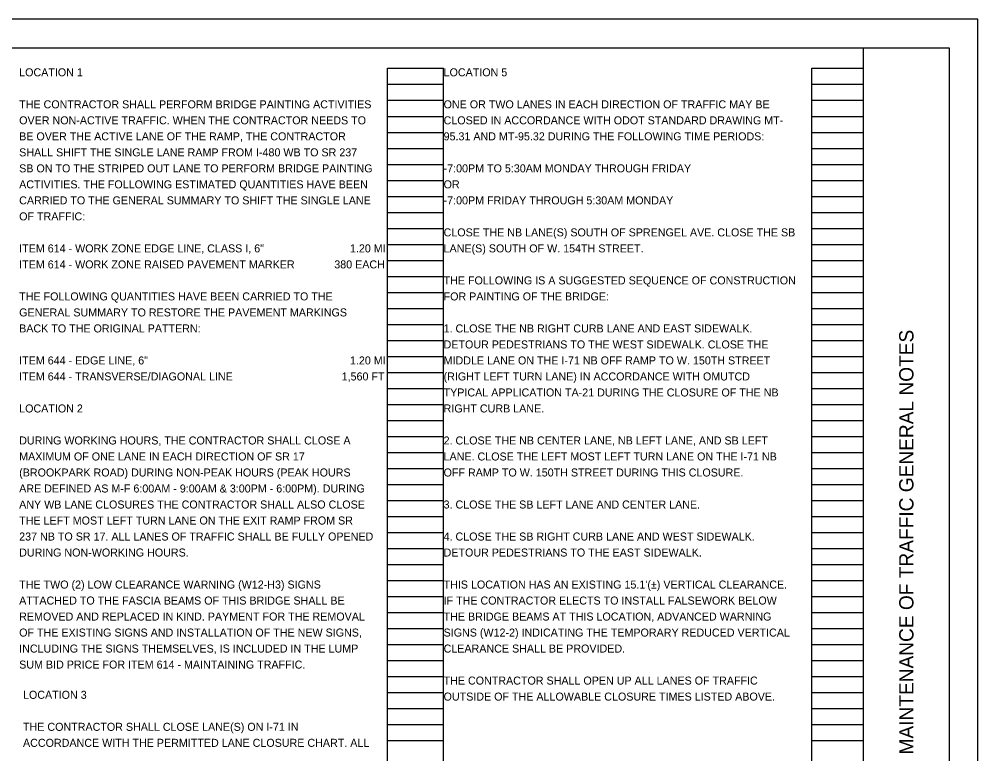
# Model space of a CAD drawing. Extents: x -0.2 to 33.8, y 0.1 to 22.1.
# Drawn here: x 17.04 to 33.8, y 9.27 to 22.12 of the extents above; entities that cross this region are included whole.
import ezdxf

# ---------------------------------------------------------------- set-up
doc = ezdxf.new("R2010")
doc.units = 0
for name, color, linetype in [('SH_Border', 7, 'Continuous'), ('SH_Cut_Line', 7, 'Continuous'), ('SH_Data', 7, 'Continuous'), ('SH_Text', 7, 'Continuous')]:
    doc.layers.add(name, color=color, linetype=linetype)

msp = doc.modelspace()

# ---------------------------------------------------------------- linework, layer by layer
at = {"layer": 'SH_Border'}
msp.add_line((31.798, 0.621), (31.798, 21.621), dxfattribs=at)
msp.add_lwpolyline([(1.298, 21.621), (33.298, 21.621), (33.298, 0.621), (1.298, 0.621)], close=True, dxfattribs=at)
at = {"layer": 'SH_Cut_Line'}
msp.add_lwpolyline([(-0.202, 0.121), (33.798, 0.121), (33.798, 22.121), (-0.202, 22.121)], close=True, dxfattribs=at)
at = {"layer": 'SH_Data'}
for p, q in [((23.478, 1.101), (23.478, 21.261)), ((23.478, 21.261), (24.458, 21.261)), ((24.458, 1.101), (24.458, 21.261)), ((30.898, 1.101), (30.898, 21.261)), ((30.898, 21.261), (31.798, 21.261)), ((31.798, 1.101), (31.798, 21.261)), ((23.478, 20.981), (24.458, 20.981)), ((30.898, 20.981), (31.798, 20.981)), ((23.478, 20.701), (24.458, 20.701)), ((30.898, 20.701), (31.798, 20.701)), ((23.478, 20.421), (24.458, 20.421)), ((30.898, 20.421), (31.798, 20.421)), ((23.478, 20.141), (24.458, 20.141)), ((30.898, 20.141), (31.798, 20.141)), ((23.478, 19.861), (24.458, 19.861)), ((30.898, 19.861), (31.798, 19.861)), ((23.478, 19.581), (24.458, 19.581)), ((30.898, 19.581), (31.798, 19.581)), ((23.478, 19.301), (24.458, 19.301)), ((30.898, 19.301), (31.798, 19.301)), ((23.478, 19.021), (24.458, 19.021)), ((30.898, 19.021), (31.798, 19.021)), ((23.478, 18.741), (24.458, 18.741)), ((30.898, 18.741), (31.798, 18.741)), ((23.478, 18.461), (24.458, 18.461)), ((30.898, 18.461), (31.798, 18.461)), ((23.478, 18.181), (24.458, 18.181)), ((30.898, 18.181), (31.798, 18.181)), ((23.478, 17.901), (24.458, 17.901)), ((30.898, 17.901), (31.798, 17.901)), ((23.478, 17.621), (24.458, 17.621)), ((30.898, 17.621), (31.798, 17.621)), ((23.478, 17.341), (24.458, 17.341)), ((30.898, 17.341), (31.798, 17.341)), ((23.478, 17.061), (24.458, 17.061)), ((30.898, 17.061), (31.798, 17.061)), ((23.478, 16.781), (24.458, 16.781)), ((30.898, 16.781), (31.798, 16.781)), ((23.478, 16.501), (24.458, 16.501)), ((30.898, 16.501), (31.798, 16.501)), ((23.478, 16.221), (24.458, 16.221)), ((30.898, 16.221), (31.798, 16.221)), ((23.478, 15.941), (24.458, 15.941)), ((30.898, 15.941), (31.798, 15.941)), ((23.478, 15.661), (24.458, 15.661)), ((30.898, 15.661), (31.798, 15.661)), ((23.478, 15.381), (24.458, 15.381)), ((30.898, 15.381), (31.798, 15.381)), ((23.478, 15.101), (24.458, 15.101)), ((30.898, 15.101), (31.798, 15.101)), ((23.478, 14.821), (24.458, 14.821)), ((30.898, 14.821), (31.798, 14.821)), ((23.478, 14.541), (24.458, 14.541)), ((30.898, 14.541), (31.798, 14.541)), ((23.478, 14.261), (24.458, 14.261)), ((30.898, 14.261), (31.798, 14.261)), ((23.478, 13.981), (24.458, 13.981)), ((30.898, 13.981), (31.798, 13.981)), ((23.478, 13.701), (24.458, 13.701)), ((30.898, 13.701), (31.798, 13.701)), ((23.478, 13.421), (24.458, 13.421)), ((30.898, 13.421), (31.798, 13.421)), ((23.478, 13.141), (24.458, 13.141)), ((30.898, 13.141), (31.798, 13.141)), ((23.478, 12.861), (24.458, 12.861)), ((30.898, 12.861), (31.798, 12.861)), ((23.478, 12.581), (24.458, 12.581)), ((30.898, 12.581), (31.798, 12.581)), ((23.478, 12.301), (24.458, 12.301)), ((30.898, 12.301), (31.798, 12.301)), ((23.478, 12.021), (24.458, 12.021)), ((30.898, 12.021), (31.798, 12.021)), ((23.478, 11.741), (24.458, 11.741)), ((30.898, 11.741), (31.798, 11.741)), ((23.478, 11.461), (24.458, 11.461)), ((30.898, 11.461), (31.798, 11.461)), ((23.478, 11.181), (24.458, 11.181)), ((30.898, 11.181), (31.798, 11.181)), ((23.478, 10.901), (24.458, 10.901)), ((30.898, 10.901), (31.798, 10.901)), ((23.478, 10.621), (24.458, 10.621)), ((30.898, 10.621), (31.798, 10.621)), ((23.478, 10.341), (24.458, 10.341)), ((30.898, 10.341), (31.798, 10.341)), ((23.478, 10.061), (24.458, 10.061)), ((30.898, 10.061), (31.798, 10.061)), ((23.478, 9.781), (24.458, 9.781)), ((30.898, 9.781), (31.798, 9.781)), ((23.478, 9.501), (24.458, 9.501)), ((30.898, 9.501), (31.798, 9.501))]:
    msp.add_line(p, q, dxfattribs=at)

# ---------------------------------------------------------------- texts
msp.add_text('MAINTENANCE OF TRAFFIC GENERAL NOTES', height=0.25, rotation=90, dxfattribs=at).set_placement((32.673, 9.258))
at = {"layer": 'SH_Text'}
for s, p in [('LOCATION 1', (17.038, 21.121)), ('LOCATION 5', (24.458, 21.121)), ('THE CONTRACTOR SHALL PERFORM BRIDGE PAINTING ACTIVITIES ', (17.038, 20.561)), ('ONE OR TWO LANES IN EACH DIRECTION OF TRAFFIC MAY BE ', (24.458, 20.561)), ('OVER NON-ACTIVE TRAFFIC. WHEN THE CONTRACTOR NEEDS TO ', (17.038, 20.281)), ('CLOSED IN ACCORDANCE WITH ODOT STANDARD DRAWING MT-', (24.458, 20.281)), ('BE OVER THE ACTIVE LANE OF THE RAMP, THE CONTRACTOR ', (17.038, 20.001)), ('95.31 AND MT-95.32 DURING THE FOLLOWING TIME PERIODS:', (24.458, 20.001)), ('SHALL SHIFT THE SINGLE LANE RAMP FROM I-480 WB TO SR 237 ', (17.038, 19.721)), ('SB ON TO THE STRIPED OUT LANE TO PERFORM BRIDGE PAINTING ', (17.038, 19.441)), ('-7:00PM TO 5:30AM MONDAY THROUGH FRIDAY', (24.458, 19.441)), ('ACTIVITIES. THE FOLLOWING ESTIMATED QUANTITIES HAVE BEEN ', (17.038, 19.161)), ('OR', (24.458, 19.161)), ('CARRIED TO THE GENERAL SUMMARY TO SHIFT THE SINGLE LANE ', (17.038, 18.881)), ('-7:00PM FRIDAY THROUGH 5:30AM MONDAY', (24.458, 18.881)), ('OF TRAFFIC:', (17.038, 18.601)), ('CLOSE THE NB LANE(S) SOUTH OF SPRENGEL AVE. CLOSE THE SB ', (24.458, 18.321)), ('ITEM 614 - WORK ZONE EDGE LINE, CLASS I, 6"', (17.038, 18.041)), ('1.20 MI', (22.821, 18.041)), ('LANE(S) SOUTH OF W. 154TH STREET. ', (24.458, 18.041)), ('ITEM 614 - WORK ZONE RAISED PAVEMENT MARKER', (17.038, 17.761)), ('380 EACH', (22.547, 17.761)), ('THE FOLLOWING IS A SUGGESTED SEQUENCE OF CONSTRUCTION ', (24.458, 17.481)), ('THE FOLLOWING QUANTITIES HAVE BEEN CARRIED TO THE ', (17.038, 17.201)), ('FOR PAINTING OF THE BRIDGE:', (24.458, 17.201)), ('GENERAL SUMMARY TO RESTORE THE PAVEMENT MARKINGS ', (17.038, 16.921)), ('BACK TO THE ORIGINAL PATTERN:', (17.038, 16.641)), ('1. CLOSE THE NB RIGHT CURB LANE AND EAST SIDEWALK. ', (24.458, 16.641)), ('DETOUR PEDESTRIANS TO THE WEST SIDEWALK. CLOSE THE ', (24.458, 16.361)), ('ITEM 644 - EDGE LINE, 6"', (17.038, 16.081)), ('1.20 MI', (22.821, 16.081)), ('MIDDLE LANE ON THE I-71 NB OFF RAMP TO W. 150TH STREET ', (24.458, 16.081)), ('ITEM 644 - TRANSVERSE/DIAGONAL LINE', (17.038, 15.801)), ('1,560 FT', (22.676, 15.801)), ('(RIGHT LEFT TURN LANE) IN ACCORDANCE WITH OMUTCD ', (24.458, 15.801)), ('TYPICAL APPLICATION TA-21 DURING THE CLOSURE OF THE NB ', (24.458, 15.521)), ('LOCATION 2', (17.038, 15.241)), ('RIGHT CURB LANE.', (24.458, 15.241)), ('DURING WORKING HOURS, THE CONTRACTOR SHALL CLOSE A ', (17.038, 14.681)), ('2. CLOSE THE NB CENTER LANE, NB LEFT LANE, AND SB LEFT ', (24.458, 14.681)), ('MAXIMUM OF ONE LANE IN EACH DIRECTION OF SR 17 ', (17.038, 14.401)), ('LANE. CLOSE THE LEFT MOST LEFT TURN LANE ON THE I-71 NB ', (24.458, 14.401)), ('(BROOKPARK ROAD) DURING NON-PEAK HOURS (PEAK HOURS ', (17.038, 14.121)), ('OFF RAMP TO W. 150TH STREET DURING THIS CLOSURE.', (24.458, 14.121)), ('ARE DEFINED AS M-F 6:00AM - 9:00AM & 3:00PM - 6:00PM). DURING ', (17.038, 13.841)), ('ANY WB LANE CLOSURES THE CONTRACTOR SHALL ALSO CLOSE ', (17.038, 13.561)), ('3. CLOSE THE SB LEFT LANE AND CENTER LANE.', (24.458, 13.561)), ('THE LEFT MOST LEFT TURN LANE ON THE EXIT RAMP FROM SR ', (17.038, 13.281)), ('237 NB TO SR 17. ALL LANES OF TRAFFIC SHALL BE FULLY OPENED ', (17.038, 13.001)), ('4. CLOSE THE SB RIGHT CURB LANE AND WEST SIDEWALK. ', (24.458, 13.001)), ('DURING NON-WORKING HOURS. ', (17.038, 12.721)), ('DETOUR PEDESTRIANS TO THE EAST SIDEWALK.', (24.458, 12.721)), ('THE TWO (2) LOW CLEARANCE WARNING (W12-H3) SIGNS ', (17.038, 12.161)), ("THIS LOCATION HAS AN EXISTING 15.1'(±) VERTICAL CLEARANCE. ", (24.458, 12.161)), ('ATTACHED TO THE FASCIA BEAMS OF THIS BRIDGE SHALL BE ', (17.038, 11.881)), ('IF THE CONTRACTOR ELECTS TO INSTALL FALSEWORK BELOW ', (24.458, 11.881)), ('REMOVED AND REPLACED IN KIND. PAYMENT FOR THE REMOVAL ', (17.038, 11.601)), ('THE BRIDGE BEAMS AT THIS LOCATION, ADVANCED WARNING ', (24.458, 11.601)), ('OF THE EXISTING SIGNS AND INSTALLATION OF THE NEW SIGNS, ', (17.038, 11.321)), ('SIGNS (W12-2) INDICATING THE TEMPORARY REDUCED VERTICAL ', (24.458, 11.321)), ('INCLUDING THE SIGNS THEMSELVES, IS INCLUDED IN THE LUMP ', (17.038, 11.041)), ('CLEARANCE SHALL BE PROVIDED.', (24.458, 11.041)), ('SUM BID PRICE FOR ITEM 614 - MAINTAINING TRAFFIC.', (17.038, 10.761)), ('THE CONTRACTOR SHALL OPEN UP ALL LANES OF TRAFFIC ', (24.458, 10.481)), ('LOCATION 3', (17.105, 10.232)), ('OUTSIDE OF THE ALLOWABLE CLOSURE TIMES LISTED ABOVE.', (24.458, 10.201)), ('THE CONTRACTOR SHALL CLOSE LANE(S) ON I-71 IN ', (17.105, 9.672)), ('ACCORDANCE WITH THE PERMITTED LANE CLOSURE CHART. ALL ', (17.105, 9.392))]:
    msp.add_text(s, height=0.14, dxfattribs=at).set_placement(p)

doc.saveas('drawing.dxf')
